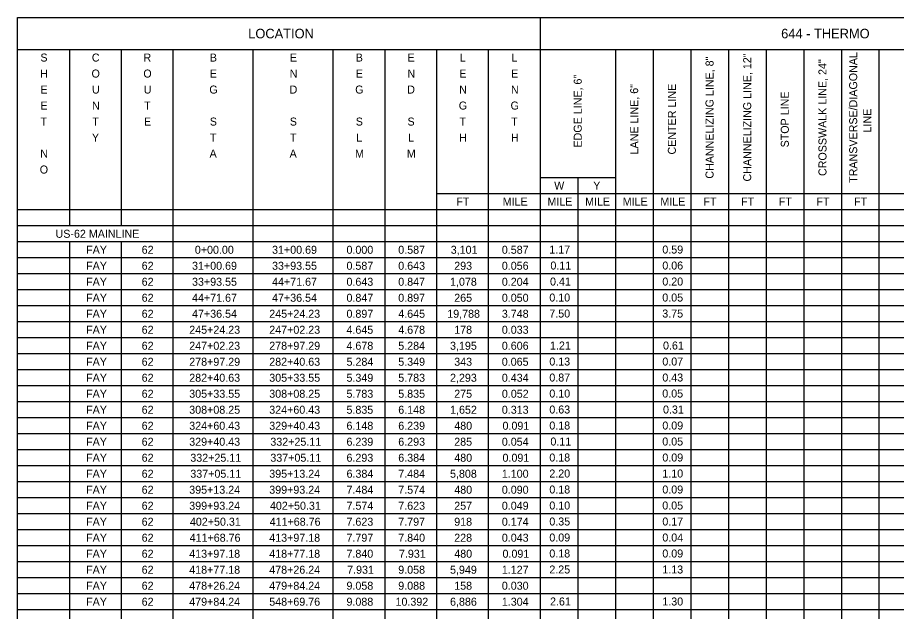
# Model space of a CAD drawing. Extents: x 12522 to 13018, y 1124 to 1902.
# Drawn here: x 12873.15 to 12888.52, y 1791.12 to 1801.51 of the extents above; entities that cross this region are included whole.
import ezdxf

# ---------------------------------------------------------------- set-up
doc = ezdxf.new("R2010")
doc.units = 0
for name, color, linetype in [('SC_Scratch1', 7, 'Continuous'), ('SH_Data', 7, 'Continuous'), ('SH_Text', 7, 'Continuous')]:
    doc.layers.add(name, color=color, linetype=linetype)

msp = doc.modelspace()

# ---------------------------------------------------------------- linework, layer by layer
at = {"layer": 'SC_Scratch1'}
msp.add_lwpolyline([(12873.148, 1801.509), (12903.648, 1801.509), (12903.648, 1780.509), (12873.148, 1780.509)], close=True, dxfattribs=at)
at = {"layer": 'SH_Data'}
for p, q in [((12882.289, 1801.509), (12882.289, 1780.525)), ((12873.148, 1800.949), (12903.668, 1800.949)), ((12874.054, 1800.949), (12874.054, 1797.869)), ((12874.96, 1800.949), (12874.96, 1797.869)), ((12875.865, 1800.949), (12875.865, 1781.069)), ((12877.265, 1800.949), (12877.265, 1781.069)), ((12878.665, 1800.949), (12878.665, 1781.069)), ((12879.571, 1800.949), (12879.571, 1781.069)), ((12880.477, 1800.949), (12880.477, 1781.069)), ((12881.383, 1800.949), (12881.383, 1781.069)), ((12883.607, 1800.949), (12883.607, 1780.525)), ((12884.265, 1800.949), (12884.265, 1780.525)), ((12884.924, 1800.949), (12884.924, 1780.525)), ((12885.583, 1800.949), (12885.583, 1780.525)), ((12886.242, 1800.949), (12886.242, 1780.525)), ((12886.901, 1800.949), (12886.901, 1780.525)), ((12887.56, 1800.949), (12887.56, 1780.525)), ((12888.218, 1800.949), (12888.218, 1780.525)), ((12882.289, 1798.709), (12883.607, 1798.709)), ((12882.948, 1798.709), (12882.948, 1781.069)), ((12880.477, 1798.429), (12903.668, 1798.429)), ((12873.148, 1798.149), (12903.668, 1798.149)), ((12873.148, 1797.869), (12903.668, 1797.869)), ((12873.148, 1797.589), (12903.668, 1797.589)), ((12874.054, 1797.589), (12874.054, 1781.069)), ((12874.96, 1797.589), (12874.96, 1781.069)), ((12873.148, 1797.309), (12903.668, 1797.309)), ((12873.148, 1797.029), (12903.668, 1797.029)), ((12873.148, 1796.749), (12903.668, 1796.749)), ((12873.148, 1796.469), (12903.668, 1796.469)), ((12873.148, 1796.189), (12903.668, 1796.189)), ((12873.148, 1795.909), (12903.668, 1795.909)), ((12873.148, 1795.629), (12903.668, 1795.629)), ((12873.148, 1795.349), (12903.668, 1795.349)), ((12873.148, 1795.069), (12903.668, 1795.069)), ((12873.148, 1794.789), (12903.668, 1794.789)), ((12873.148, 1794.509), (12903.668, 1794.509)), ((12873.148, 1794.229), (12903.668, 1794.229)), ((12873.148, 1793.949), (12903.668, 1793.949)), ((12873.148, 1793.669), (12903.668, 1793.669)), ((12873.148, 1793.389), (12903.668, 1793.389)), ((12873.148, 1793.109), (12903.668, 1793.109)), ((12873.148, 1792.829), (12903.668, 1792.829)), ((12873.148, 1792.549), (12903.668, 1792.549)), ((12873.148, 1792.269), (12903.668, 1792.269)), ((12873.148, 1791.989), (12903.668, 1791.989)), ((12873.148, 1791.709), (12903.668, 1791.709)), ((12873.148, 1791.429), (12903.668, 1791.429)), ((12873.148, 1791.149), (12903.668, 1791.149))]:
    msp.add_line(p, q, dxfattribs=at)

# ---------------------------------------------------------------- texts
at = {"layer": 'SH_Text'}
for s, height, p in [('LOCATION', 0.168, (12877.183, 1801.145)), ('644 - THERMO', 0.168, (12886.507, 1801.145)), ('S', 0.14, (12873.547, 1800.739)), ('C', 0.14, (12874.447, 1800.739)), ('R', 0.14, (12875.35, 1800.739)), ('B', 0.14, (12876.511, 1800.739)), ('E', 0.14, (12877.911, 1800.739)), ('B', 0.14, (12879.064, 1800.739)), ('E', 0.14, (12879.97, 1800.739)), ('L', 0.14, (12880.884, 1800.739)), ('L', 0.14, (12881.79, 1800.739)), ('H', 0.14, (12873.544, 1800.459)), ('O', 0.14, (12874.442, 1800.459)), ('O', 0.14, (12875.348, 1800.459)), ('E', 0.14, (12876.511, 1800.459)), ('N', 0.14, (12877.909, 1800.459)), ('E', 0.14, (12879.064, 1800.459)), ('N', 0.14, (12879.968, 1800.459)), ('E', 0.14, (12880.876, 1800.459)), ('E', 0.14, (12881.782, 1800.459)), ('E', 0.14, (12873.547, 1800.179)), ('U', 0.14, (12874.45, 1800.179)), ('U', 0.14, (12875.356, 1800.179)), ('G', 0.14, (12876.503, 1800.179)), ('D', 0.14, (12877.907, 1800.179)), ('G', 0.14, (12879.055, 1800.179)), ('D', 0.14, (12879.965, 1800.179)), ('N', 0.14, (12880.874, 1800.179)), ('N', 0.14, (12881.78, 1800.179)), ('E', 0.14, (12873.547, 1799.899)), ('N', 0.14, (12874.45, 1799.899)), ('T', 0.14, (12875.361, 1799.899)), ('G', 0.14, (12880.867, 1799.899)), ('G', 0.14, (12881.773, 1799.899)), ('T', 0.14, (12873.549, 1799.619)), ('T', 0.14, (12874.455, 1799.619)), ('E', 0.14, (12875.359, 1799.619)), ('S', 0.14, (12876.511, 1799.619)), ('S', 0.14, (12877.911, 1799.619)), ('S', 0.14, (12879.064, 1799.619)), ('S', 0.14, (12879.97, 1799.619)), ('T', 0.14, (12880.878, 1799.619)), ('T', 0.14, (12881.784, 1799.619)), ('Y', 0.14, (12874.449, 1799.339)), ('T', 0.14, (12876.513, 1799.339)), ('T', 0.14, (12877.913, 1799.339)), ('L', 0.14, (12879.073, 1799.339)), ('L', 0.14, (12879.978, 1799.339)), ('H', 0.14, (12880.874, 1799.339)), ('H', 0.14, (12881.78, 1799.339)), ('N', 0.14, (12873.544, 1799.059)), ('A', 0.14, (12876.507, 1799.059)), ('A', 0.14, (12877.907, 1799.059)), ('M', 0.14, (12879.052, 1799.059)), ('M', 0.14, (12879.958, 1799.059)), ('O', 0.14, (12873.536, 1798.779)), ('W', 0.14, (12882.536, 1798.499)), ('Y', 0.14, (12883.219, 1798.499)), ('FT', 0.14, (12880.824, 1798.219)), ('MILE', 0.14, (12881.635, 1798.219)), ('MILE', 0.14, (12882.418, 1798.219)), ('MILE', 0.14, (12883.077, 1798.219)), ('MILE', 0.14, (12883.735, 1798.219)), ('MILE', 0.14, (12884.394, 1798.219)), ('FT', 0.14, (12885.148, 1798.219)), ('FT', 0.14, (12885.807, 1798.219)), ('FT', 0.14, (12886.466, 1798.219)), ('FT', 0.14, (12887.124, 1798.219)), ('FT', 0.14, (12887.783, 1798.219)), ('US-62 MAINLINE', 0.14, (12873.812, 1797.655)), ('FAY', 0.14, (12874.347, 1797.375)), ('62', 0.14, (12875.319, 1797.375)), ('0+00.00', 0.14, (12876.249, 1797.375)), ('31+00.69', 0.14, (12877.6, 1797.375)), ('0.000', 0.14, (12878.902, 1797.375)), ('0.587', 0.14, (12879.808, 1797.375)), ('3,101', 0.14, (12880.726, 1797.375)), ('0.587', 0.14, (12881.62, 1797.375)), ('1.17', 0.14, (12882.451, 1797.379)), ('0.59', 0.14, (12884.428, 1797.379)), ('FAY', 0.14, (12874.347, 1797.095)), ('62', 0.14, (12875.319, 1797.095)), ('31+00.69', 0.14, (12876.2, 1797.095)), ('33+93.55', 0.14, (12877.6, 1797.095)), ('0.587', 0.14, (12878.902, 1797.095)), ('0.643', 0.14, (12879.808, 1797.095)), ('293', 0.14, (12880.787, 1797.095)), ('0.056', 0.14, (12881.62, 1797.095)), ('0.11', 0.14, (12882.47, 1797.099)), ('0.06', 0.14, (12884.428, 1797.099)), ('FAY', 0.14, (12874.347, 1796.815)), ('62', 0.14, (12875.319, 1796.815)), ('33+93.55', 0.14, (12876.2, 1796.815)), ('44+71.67', 0.14, (12877.6, 1796.815)), ('0.643', 0.14, (12878.902, 1796.815)), ('0.847', 0.14, (12879.808, 1796.815)), ('1,078', 0.14, (12880.714, 1796.815)), ('0.204', 0.14, (12881.62, 1796.815)), ('0.41', 0.14, (12882.463, 1796.819)), ('0.20', 0.14, (12884.428, 1796.819)), ('FAY', 0.14, (12874.347, 1796.535)), ('62', 0.14, (12875.319, 1796.535)), ('44+71.67', 0.14, (12876.2, 1796.535)), ('47+36.54', 0.14, (12877.6, 1796.535)), ('0.847', 0.14, (12878.902, 1796.535)), ('0.897', 0.14, (12879.808, 1796.535)), ('265', 0.14, (12880.787, 1796.535)), ('0.050', 0.14, (12881.62, 1796.535)), ('0.10', 0.14, (12882.451, 1796.539)), ('0.05', 0.14, (12884.427, 1796.539)), ('FAY', 0.14, (12874.347, 1796.255)), ('62', 0.14, (12875.319, 1796.255)), ('47+36.54', 0.14, (12876.2, 1796.255)), ('245+24.23', 0.14, (12877.551, 1796.255)), ('0.897', 0.14, (12878.902, 1796.255)), ('4.645', 0.14, (12879.808, 1796.255)), ('19,788', 0.14, (12880.665, 1796.255)), ('3.748', 0.14, (12881.62, 1796.255)), ('7.50', 0.14, (12882.451, 1796.259)), ('3.75', 0.14, (12884.427, 1796.259)), ('FAY', 0.14, (12874.347, 1795.975)), ('62', 0.14, (12875.319, 1795.975)), ('245+24.23', 0.14, (12876.151, 1795.975)), ('247+02.23', 0.14, (12877.551, 1795.975)), ('4.645', 0.14, (12878.902, 1795.975)), ('4.678', 0.14, (12879.808, 1795.975)), ('178', 0.14, (12880.787, 1795.975)), ('0.033', 0.14, (12881.62, 1795.975)), ('FAY', 0.14, (12874.347, 1795.695)), ('62', 0.14, (12875.319, 1795.695)), ('247+02.23', 0.14, (12876.151, 1795.695)), ('278+97.29', 0.14, (12877.551, 1795.695)), ('4.678', 0.14, (12878.902, 1795.695)), ('5.284', 0.14, (12879.808, 1795.695)), ('3,195', 0.14, (12880.714, 1795.695)), ('0.606', 0.14, (12881.62, 1795.695)), ('1.21', 0.14, (12882.463, 1795.699)), ('0.61', 0.14, (12884.44, 1795.699)), ('FAY', 0.14, (12874.347, 1795.415)), ('62', 0.14, (12875.319, 1795.415)), ('278+97.29', 0.14, (12876.151, 1795.415)), ('282+40.63', 0.14, (12877.551, 1795.415)), ('5.284', 0.14, (12878.903, 1795.415)), ('5.349', 0.14, (12879.808, 1795.415)), ('343', 0.14, (12880.787, 1795.415)), ('0.065', 0.14, (12881.619, 1795.415)), ('0.13', 0.14, (12882.451, 1795.419)), ('0.07', 0.14, (12884.428, 1795.419)), ('0.87', 0.14, (12882.451, 1795.139)), ('0.43', 0.14, (12884.428, 1795.139)), ('FAY', 0.14, (12874.347, 1795.135)), ('62', 0.14, (12875.319, 1795.135)), ('282+40.63', 0.14, (12876.151, 1795.135)), ('305+33.55', 0.14, (12877.551, 1795.135)), ('5.349', 0.14, (12878.902, 1795.135)), ('5.783', 0.14, (12879.808, 1795.135)), ('2,293', 0.14, (12880.714, 1795.135)), ('0.434', 0.14, (12881.62, 1795.135)), ('FAY', 0.14, (12874.347, 1794.855)), ('62', 0.14, (12875.319, 1794.855)), ('305+33.55', 0.14, (12876.151, 1794.855)), ('308+08.25', 0.14, (12877.551, 1794.855)), ('5.783', 0.14, (12878.902, 1794.855)), ('5.835', 0.14, (12879.808, 1794.855)), ('275', 0.14, (12880.787, 1794.855)), ('0.052', 0.14, (12881.621, 1794.855)), ('0.10', 0.14, (12882.451, 1794.859)), ('0.05', 0.14, (12884.427, 1794.859)), ('FAY', 0.14, (12874.347, 1794.575)), ('62', 0.14, (12875.319, 1794.575)), ('308+08.25', 0.14, (12876.151, 1794.575)), ('324+60.43', 0.14, (12877.551, 1794.575)), ('5.835', 0.14, (12878.902, 1794.575)), ('6.148', 0.14, (12879.808, 1794.575)), ('1,652', 0.14, (12880.715, 1794.575)), ('0.313', 0.14, (12881.62, 1794.575)), ('0.63', 0.14, (12882.451, 1794.579)), ('0.31', 0.14, (12884.44, 1794.579)), ('FAY', 0.14, (12874.347, 1794.295)), ('62', 0.14, (12875.319, 1794.295)), ('324+60.43', 0.14, (12876.151, 1794.295)), ('329+40.43', 0.14, (12877.551, 1794.295)), ('6.148', 0.14, (12878.902, 1794.295)), ('6.239', 0.14, (12879.808, 1794.295)), ('480', 0.14, (12880.788, 1794.295)), ('0.091', 0.14, (12881.632, 1794.295)), ('0.18', 0.14, (12882.451, 1794.299)), ('0.09', 0.14, (12884.428, 1794.299)), ('FAY', 0.14, (12874.347, 1794.015)), ('62', 0.14, (12875.319, 1794.015)), ('329+40.43', 0.14, (12876.151, 1794.015)), ('332+25.11', 0.14, (12877.57, 1794.015)), ('6.239', 0.14, (12878.902, 1794.015)), ('6.293', 0.14, (12879.808, 1794.015)), ('285', 0.14, (12880.787, 1794.015)), ('0.054', 0.14, (12881.62, 1794.015)), ('0.11', 0.14, (12882.47, 1794.019)), ('0.05', 0.14, (12884.427, 1794.019)), ('FAY', 0.14, (12874.347, 1793.735)), ('62', 0.14, (12875.319, 1793.735)), ('332+25.11', 0.14, (12876.17, 1793.735)), ('337+05.11', 0.14, (12877.57, 1793.735)), ('6.293', 0.14, (12878.902, 1793.735)), ('6.384', 0.14, (12879.808, 1793.735)), ('480', 0.14, (12880.788, 1793.735)), ('0.091', 0.14, (12881.632, 1793.735)), ('0.18', 0.14, (12882.451, 1793.739)), ('0.09', 0.14, (12884.428, 1793.739)), ('FAY', 0.14, (12874.347, 1793.455)), ('62', 0.14, (12875.319, 1793.455)), ('337+05.11', 0.14, (12876.17, 1793.455)), ('395+13.24', 0.14, (12877.551, 1793.455)), ('6.384', 0.14, (12878.903, 1793.455)), ('7.484', 0.14, (12879.808, 1793.455)), ('5,808', 0.14, (12880.714, 1793.455)), ('1.100', 0.14, (12881.62, 1793.455)), ('2.20', 0.14, (12882.451, 1793.459)), ('1.10', 0.14, (12884.428, 1793.459)), ('FAY', 0.14, (12874.347, 1793.175)), ('62', 0.14, (12875.319, 1793.175)), ('395+13.24', 0.14, (12876.151, 1793.175)), ('399+93.24', 0.14, (12877.551, 1793.175)), ('7.484', 0.14, (12878.903, 1793.175)), ('7.574', 0.14, (12879.808, 1793.175)), ('480', 0.14, (12880.788, 1793.175)), ('0.090', 0.14, (12881.62, 1793.175)), ('0.18', 0.14, (12882.451, 1793.179)), ('0.09', 0.14, (12884.428, 1793.179)), ('FAY', 0.14, (12874.347, 1792.895)), ('62', 0.14, (12875.319, 1792.895)), ('399+93.24', 0.14, (12876.151, 1792.895)), ('402+50.31', 0.14, (12877.563, 1792.895)), ('7.574', 0.14, (12878.903, 1792.895)), ('7.623', 0.14, (12879.808, 1792.895)), ('257', 0.14, (12880.787, 1792.895)), ('0.049', 0.14, (12881.62, 1792.895)), ('0.10', 0.14, (12882.451, 1792.899)), ('0.05', 0.14, (12884.427, 1792.899)), ('FAY', 0.14, (12874.347, 1792.615)), ('62', 0.14, (12875.319, 1792.615)), ('402+50.31', 0.14, (12876.163, 1792.615)), ('411+68.76', 0.14, (12877.558, 1792.615)), ('7.623', 0.14, (12878.902, 1792.615)), ('7.797', 0.14, (12879.808, 1792.615)), ('918', 0.14, (12880.787, 1792.615)), ('0.174', 0.14, (12881.62, 1792.615)), ('0.35', 0.14, (12882.451, 1792.619)), ('0.17', 0.14, (12884.428, 1792.619)), ('FAY', 0.14, (12874.347, 1792.335)), ('62', 0.14, (12875.319, 1792.335)), ('411+68.76', 0.14, (12876.158, 1792.335)), ('413+97.18', 0.14, (12877.551, 1792.335)), ('7.797', 0.14, (12878.902, 1792.335)), ('7.840', 0.14, (12879.808, 1792.335)), ('228', 0.14, (12880.787, 1792.335)), ('0.043', 0.14, (12881.62, 1792.335)), ('0.09', 0.14, (12882.451, 1792.339)), ('0.04', 0.14, (12884.428, 1792.339)), ('FAY', 0.14, (12874.347, 1792.055)), ('62', 0.14, (12875.319, 1792.055)), ('413+97.18', 0.14, (12876.151, 1792.055)), ('418+77.18', 0.14, (12877.551, 1792.055)), ('7.840', 0.14, (12878.902, 1792.055)), ('7.931', 0.14, (12879.82, 1792.055)), ('480', 0.14, (12880.788, 1792.055)), ('0.091', 0.14, (12881.632, 1792.055)), ('0.18', 0.14, (12882.451, 1792.059)), ('0.09', 0.14, (12884.428, 1792.059)), ('FAY', 0.14, (12874.347, 1791.775)), ('62', 0.14, (12875.319, 1791.775)), ('418+77.18', 0.14, (12876.151, 1791.775)), ('478+26.24', 0.14, (12877.551, 1791.775)), ('7.931', 0.14, (12878.914, 1791.775)), ('9.058', 0.14, (12879.808, 1791.775)), ('5,949', 0.14, (12880.714, 1791.775)), ('1.127', 0.14, (12881.62, 1791.775)), ('2.25', 0.14, (12882.451, 1791.779)), ('1.13', 0.14, (12884.428, 1791.779)), ('FAY', 0.14, (12874.347, 1791.495)), ('62', 0.14, (12875.319, 1791.495)), ('478+26.24', 0.14, (12876.151, 1791.495)), ('479+84.24', 0.14, (12877.551, 1791.495)), ('9.058', 0.14, (12878.902, 1791.495)), ('9.088', 0.14, (12879.808, 1791.495)), ('158', 0.14, (12880.787, 1791.495)), ('0.030', 0.14, (12881.62, 1791.495)), ('FAY', 0.14, (12874.347, 1791.215)), ('62', 0.14, (12875.319, 1791.215)), ('479+84.24', 0.14, (12876.151, 1791.215)), ('548+69.76', 0.14, (12877.551, 1791.215)), ('9.088', 0.14, (12878.902, 1791.215)), ('10.392', 0.14, (12879.76, 1791.215)), ('6,886', 0.14, (12880.714, 1791.215)), ('1.304', 0.14, (12881.62, 1791.215)), ('2.61', 0.14, (12882.463, 1791.219)), ('1.30', 0.14, (12884.428, 1791.219))]:
    msp.add_text(s, height=height, dxfattribs=at).set_placement(p)
for s, p in [('CHANNELIZING LINE, 8"', (12885.324, 1798.689)), ('CHANNELIZING LINE, 12"', (12885.983, 1798.64)), ('TRANSVERSE/DIAGONAL ', (12887.837, 1798.616)), ('CROSSWALK LINE, 24"', (12887.3, 1798.736)), ('EDGE LINE, 6"', (12883.018, 1799.234)), ('LANE LINE, 6"', (12884.006, 1799.114)), ('CENTER LINE', (12884.665, 1799.112)), ('STOP LINE', (12886.641, 1799.237)), ('LINE', (12888.082, 1799.498))]:
    msp.add_text(s, height=0.14, rotation=90, dxfattribs=at).set_placement(p)

doc.saveas('drawing.dxf')
